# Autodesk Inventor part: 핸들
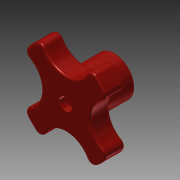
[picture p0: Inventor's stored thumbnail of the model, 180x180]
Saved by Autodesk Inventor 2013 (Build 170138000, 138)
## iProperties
Created: 2018-01
Part Number: 핸들
Material: ABS 플라스틱
Document SubType Name: Modeling
Designer: mduedu
Density: 1 g/cm^3
Author: mduedu
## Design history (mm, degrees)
sketch "스케치1"
  geometry: C1 r 10 at (0, 0); C2 r 25 at (0, 0); 1 further point
  constraints: 2 centre point, 2 coincident
  dimensions: "d0" = 20 diameter of C1; "d1" = 50 diameter of C2
extrude "돌출1" new body sketch "스케치1" distance "d2" = 15; taper "d3" = 0 deg
extrude "돌출2" join sketch "스케치1" distance "d4" = 10; taper "d5" = 0 deg
sketch "스케치2" dims "d8" = 15
  geometry: L1 (-6, -6)-(-4.5, -6); L2 (6, -6)-(6, -4.5); L3 (6, 6)-(4.5, 6); L4 (-6, 6)-(-6, 4.5); L5 (-6, -6)-(6, 6); L6 (6, -6)-(-6, 6); L7 (-4.5, 6)-(-6, 6); L8 (4.5, 6)-(-4.5, 6); L9 (6, 4.5)-(6, 6); L10 (6, -4.5)-(6, 4.5); L11 (4.5, -6)-(6, -6); L12 (-4.5, -6)-(4.5, -6); L13 (-6, -4.5)-(-6, -6); L14 (-6, 4.5)-(-6, -4.5); 2 further points
  constraints: 28 end point, 18 parallel, 9 perpendicular, 3 horizontal, 2 midpoint, 1 coincident, 10 other
  dimensions: "d6" = 12 distance of L4.start L3.start; "d7" = 12 distance of L3.start L2.start
extrude "돌출3" cut sketch "스케치2" distance "d9" = 15; taper "d10" = 0 deg
sketch "스케치3"
  geometry: C1 r 12.5 at (25, 0); 2 further points
  constraints: 2 horizontal alignment, 1 centre point, 1 other
  dimensions: "d14" = 25 diameter of C1
extrude "돌출4" cut sketch "스케치3" stored distance "d15" = 15; taper "d16" = 0 deg
fillet "모깎기1" dims "d20" = 3
fillet "모깎기2" dims "d24" = 1
sketch "스케치4"
  geometry: 2 further points
  constraints: 1 coincident
sketch "스케치5"
  geometry: 2 further points
  constraints: 1 coincident
hole "구멍1" sketch "스케치5" at (0, 0) diameter "d25" = 3.4; stored, may be unused: countersink angle "d29" = 90 deg, drill point angle "d31" = 0 deg; dims "d26" = 6, "d27" = 6.5, "d28" = 3.4, "d30" = 8
node "솔리드1"
pattern_circular "원형 패턴1" dims angle "d18" = 360 deg
pattern_circular "원형 패턴2" dims angle "d22" = 360 deg
node "투영된 루프1"
